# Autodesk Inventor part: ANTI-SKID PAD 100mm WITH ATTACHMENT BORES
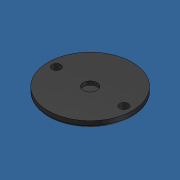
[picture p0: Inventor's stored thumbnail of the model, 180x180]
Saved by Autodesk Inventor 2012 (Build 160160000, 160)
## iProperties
Created: 2007-03
Part Number: ANTI-SKID PAD 100mm WITH ATTACHMENT BORES
Material: Rubber
Document SubType Name: Modeling
Designer: Andy Moles
Density: 0.93 g/cm^3
Mass: 41.3395 g
Surface Area: 153.283 cm^2
Volume: 44.4511 cm^3
Author: Andy Moles
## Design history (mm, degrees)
sketch "Sketch1"
  geometry: C1 r 46 at (0, 0); C2 r 4.75 at (-37, 0); C3 r 4.75 at (37, 0); 1 further point
  constraints: 3 centre point, 2 horizontal alignment, 1 coincident
  dimensions: "d0" = 92 diameter of C1; "d7" = 9.5 diameter of C2; "d8" = 9.5 diameter of C3; "d9" = 74 distance of C3.centre C2.centre; "d10" = 37 distance of point (0, 0) C2.centre (= 0.5 x d9)
extrude "Extrusion1" new body sketch "Sketch1" distance "d1" = 7; taper "d2" = 0 deg
sketch "Sketch2"
  geometry: C1 r 46 at (0, 0) reference; C2 r 7.5 at (0, 0)
  constraints: 1 centre point, 1 coincident
  dimensions: "d3" = 15 diameter of C2
extrude "Extrusion2" cut sketch "Sketch2" distance "d4" = 4; taper "d5" = 0 deg
fillet "Fillet1" dims "d6" = 2.5
body "Solid1"
